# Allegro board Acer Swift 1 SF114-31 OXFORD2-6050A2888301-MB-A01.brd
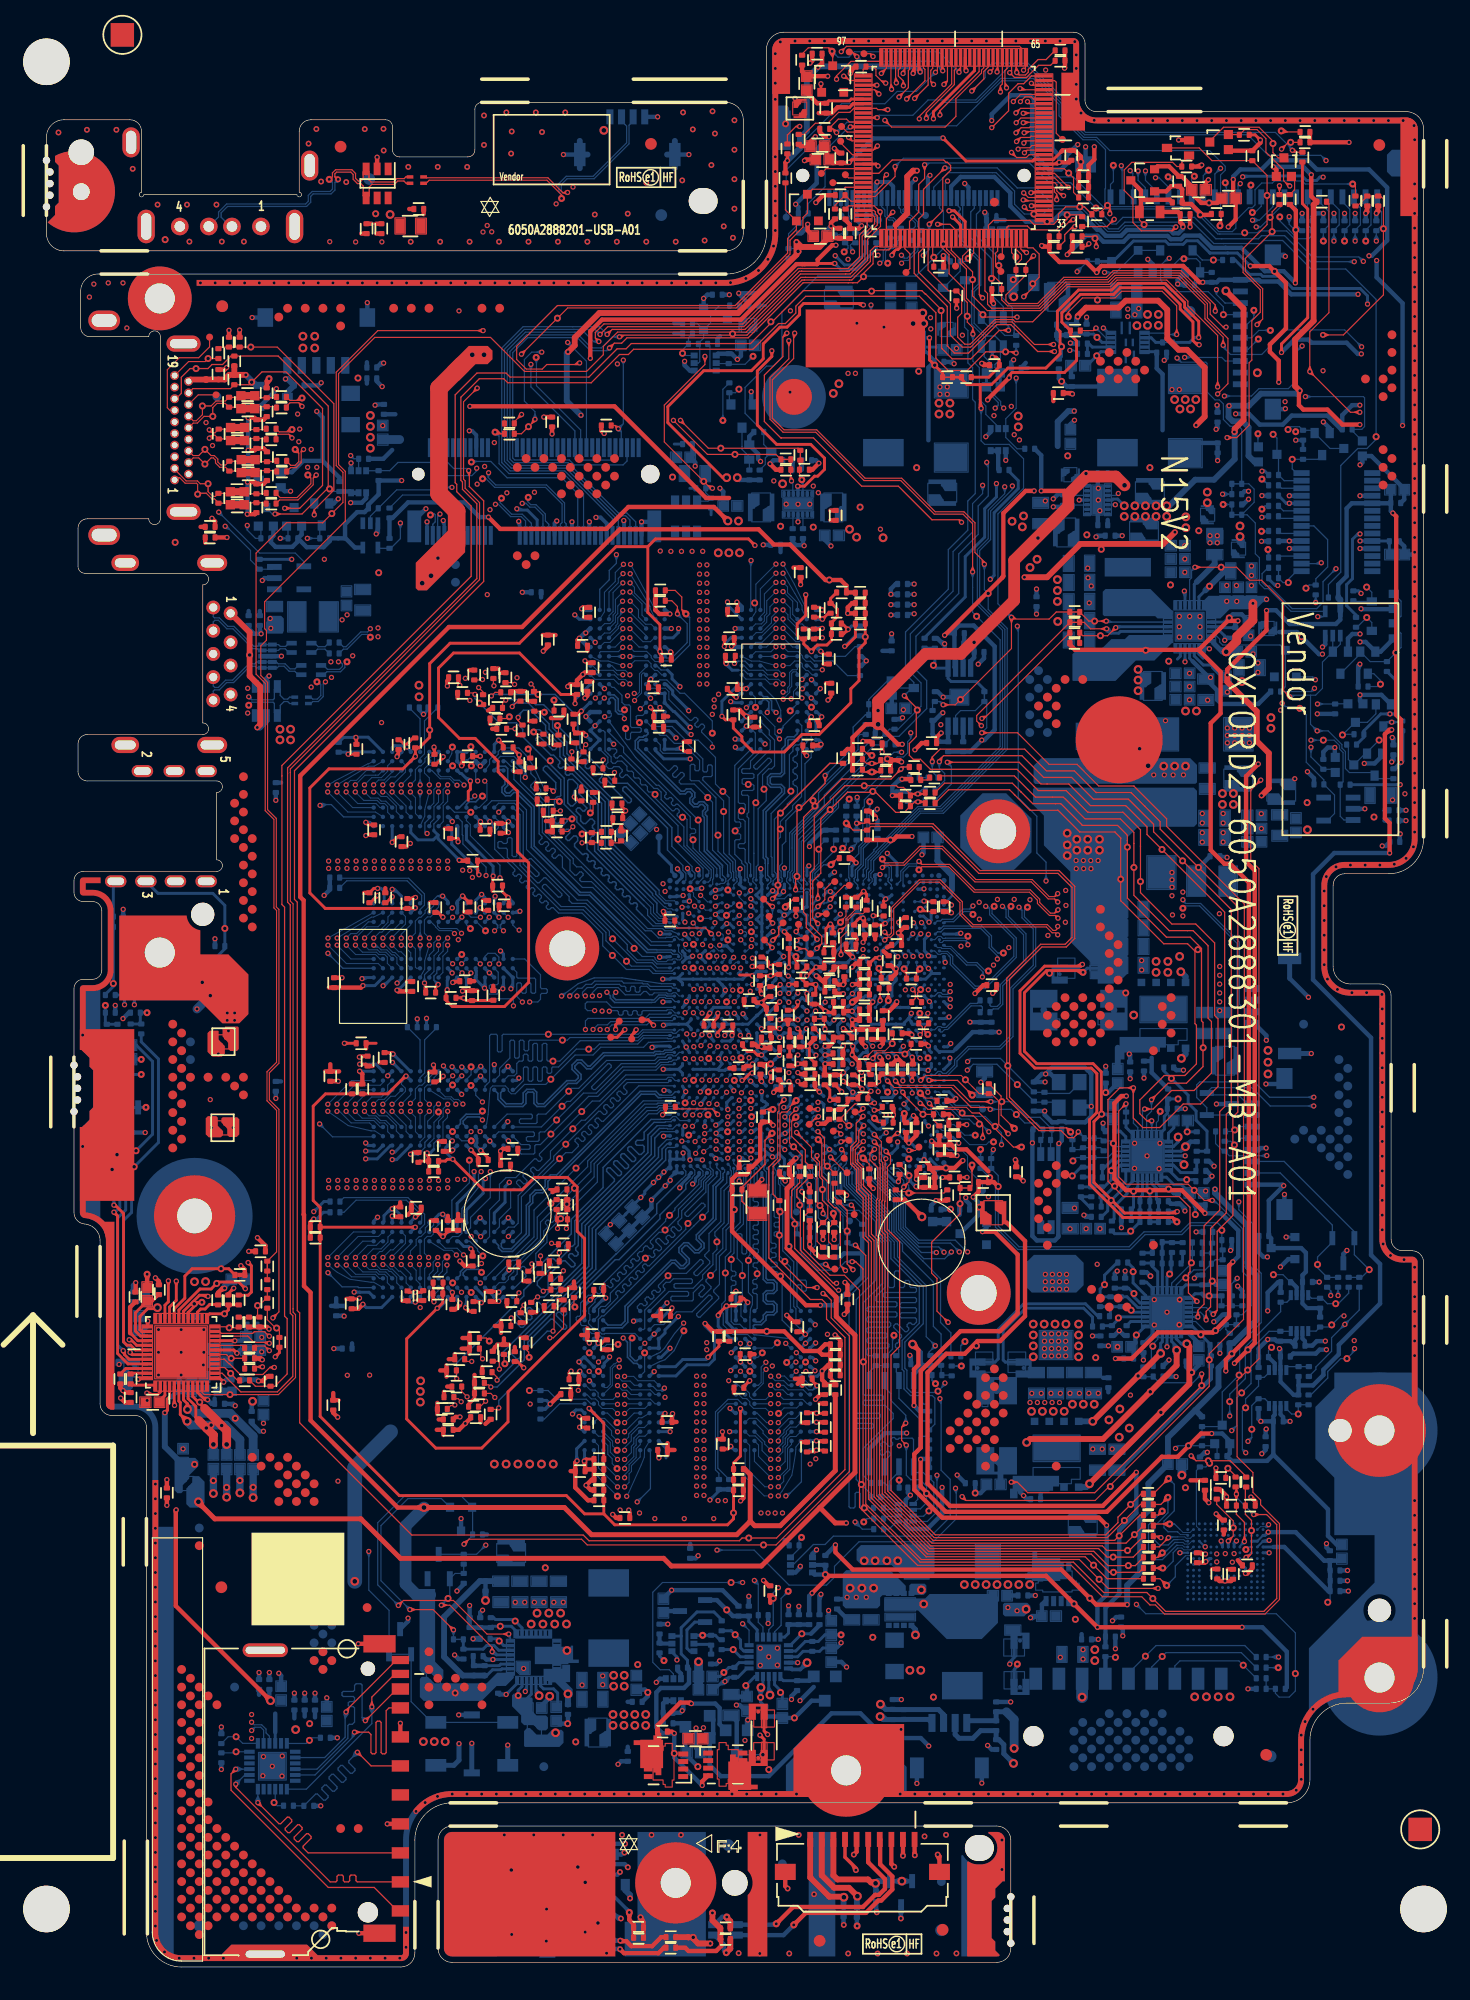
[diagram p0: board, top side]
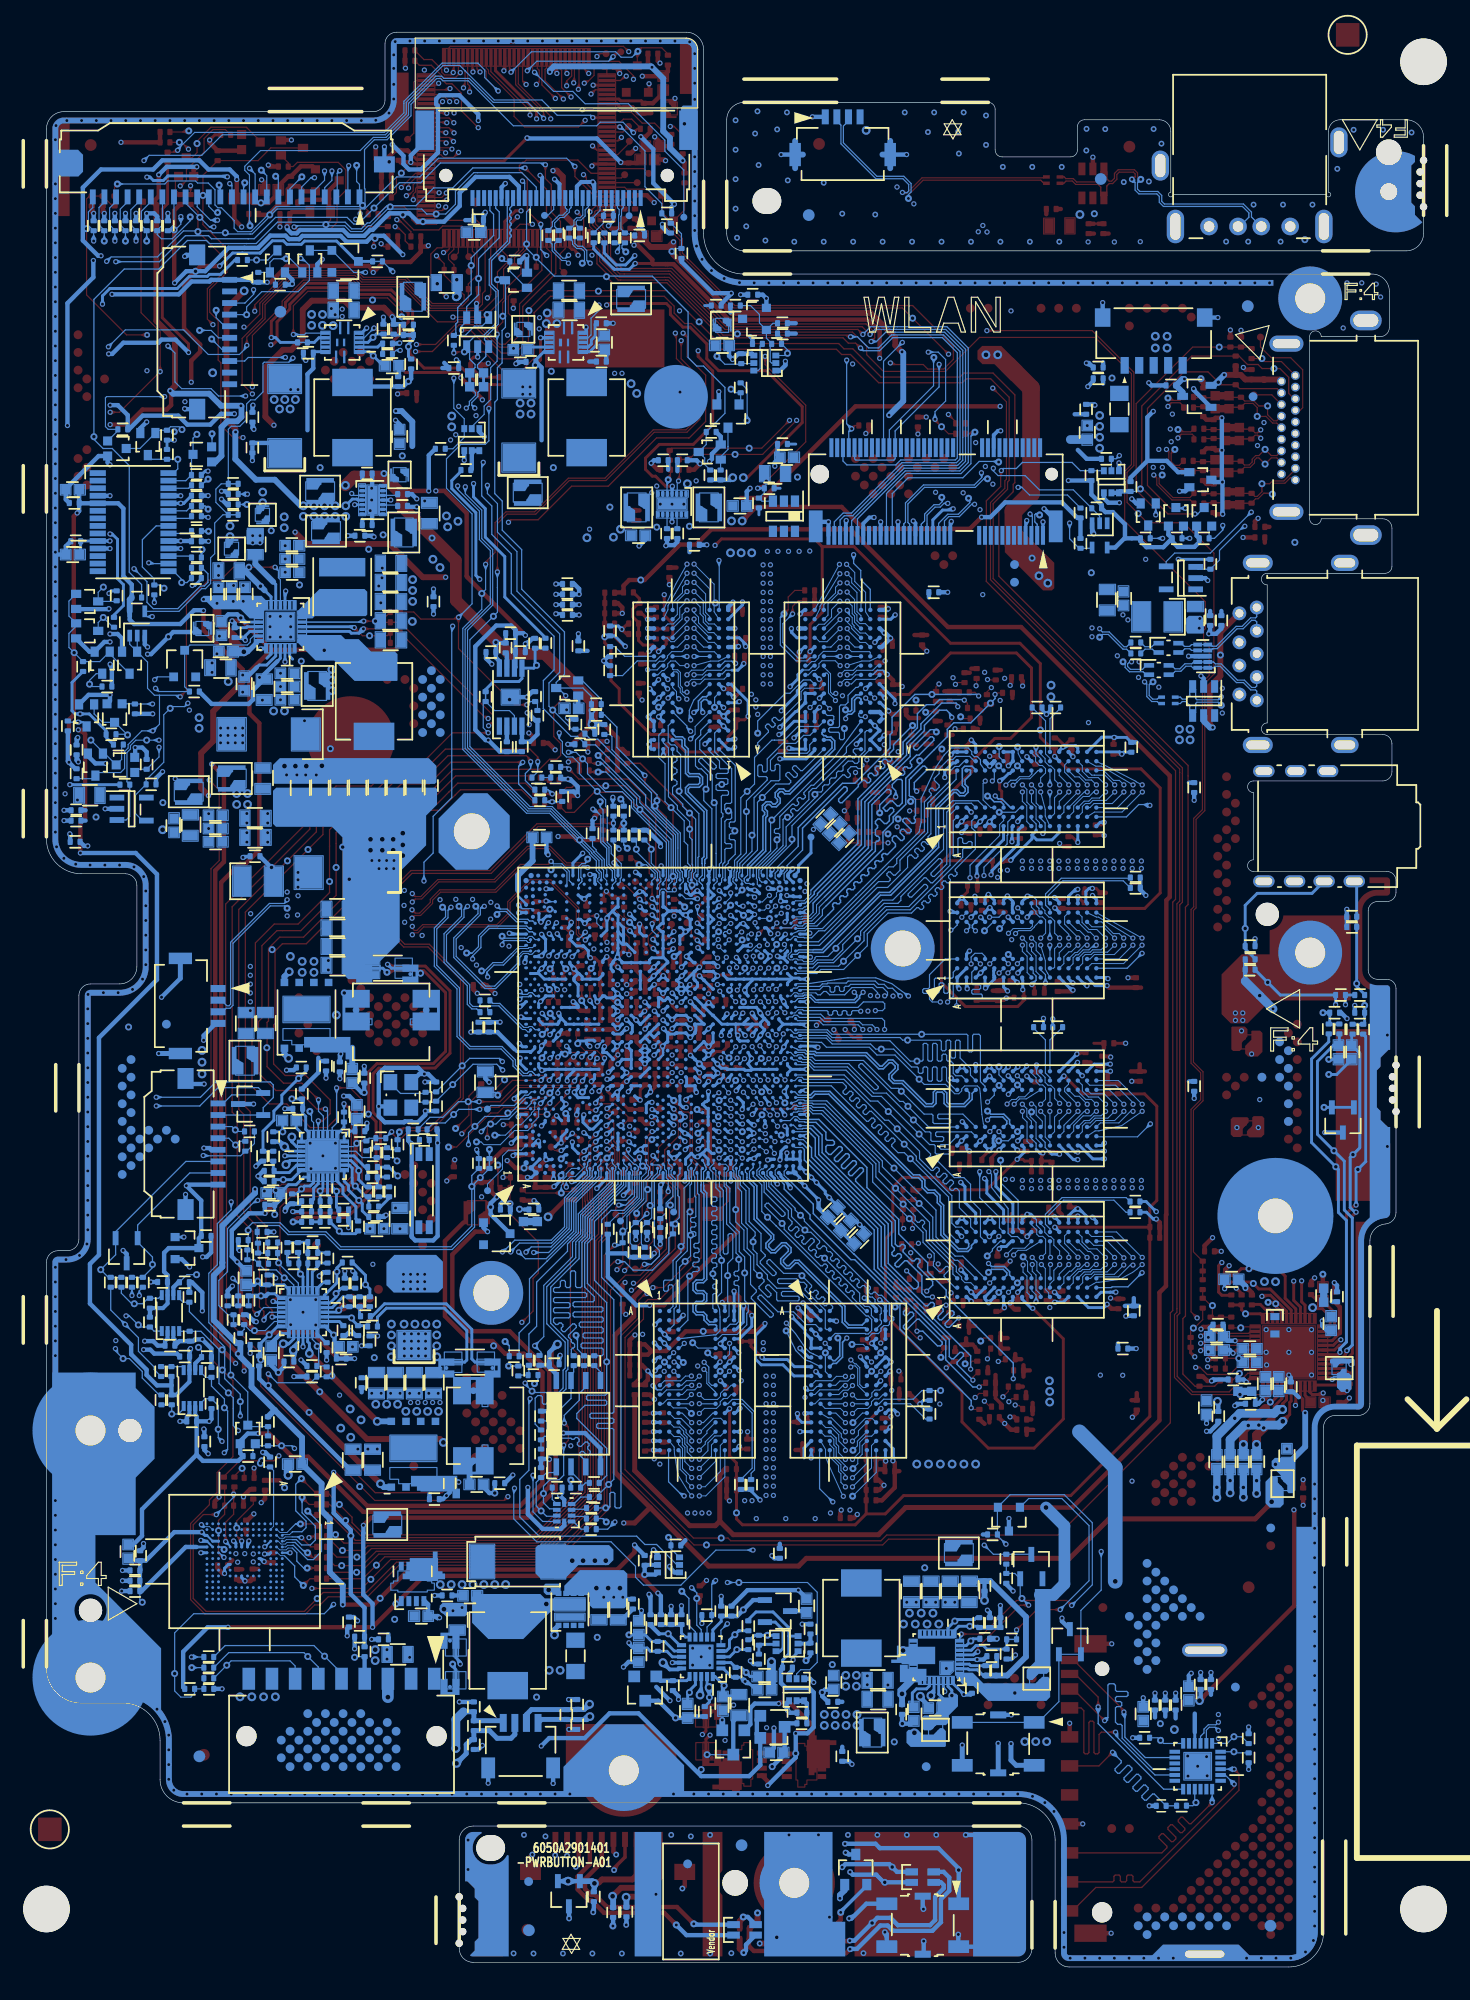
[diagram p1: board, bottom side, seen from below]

Outline 118.77 x 166.8 mm; copper layers: TOP, L2, L3, L4, L5, BOTTOM. Coordinates in mm from the lower left corner of the outline.
Outline path: 0,157.75 arc(0.44,158.81) 1.5,159.25 7.2,159.25 arc(7.91,158.96) 8.2,158.25 8.2,153 arc(8.06,152.66) 8.4,152.8 21.6,152.8 arc(21.94,152.66) 21.8,153 21.8,158.25 arc(22.09,158.96) 22.8,159.25 29.25,159.25 arc(29.67,159.07) 29.85,158.65 29.85,156.65 arc(30.03,156.23) 30.45,156.05 36.35,156.05 arc(36.77,156.23) 36.95,156.65 36.95,160.15 arc(37.13,160.57) 37.55,160.75 58.6,160.75 arc(59.66,160.31) 60.1,159.25 60.1,149.45 arc(59.66,148.39) 58.6,147.95 1.5,147.95 arc(0.44,148.39) 0,149.45 0,157.75 ; 2.37,93.65 arc(2.61,94.22) 3.17,94.45 14.68,94.45 arc(15.18,94.95) 14.68,95.45 14.68,101.25 arc(15.18,101.75) 14.68,102.25 3.53,102.25 arc(2.96,102.48) 2.72,103.05 2.72,105.45 arc(2.96,106.02) 3.53,106.25 13.49,106.25 arc(13.99,106.75) 13.49,107.25 13.49,119.15 arc(13.99,119.65) 13.49,120.15 3.33,120.15 arc(2.9,120.33) 2.72,120.75 2.72,124.05 arc(2.96,124.62) 3.53,124.85 8.82,124.85 arc(9.32,124.35) 9.82,124.85 9.82,140.55 arc(9.32,141.05) 8.82,140.55 3.75,140.55 arc(3.18,140.78) 2.95,141.35 2.95,144.45 arc(3.39,145.51) 4.45,145.95 58.6,145.95 arc(61.07,146.98) 62.1,149.45 62.1,165.3 arc(62.54,166.36) 63.6,166.8 88.58,166.8 arc(89.28,166.51) 89.58,165.8 89.58,160.95 arc(89.87,160.24) 90.58,159.95 117.28,159.95 arc(118.34,159.51) 118.77,158.45 118.77,97.25 arc(117.9,95.13) 115.77,94.25 111.98,94.25 arc(111.27,93.96) 110.98,93.25 110.98,86.25 arc(111.41,85.19) 112.48,84.75 114.98,84.75 arc(115.68,84.46) 115.98,83.75 115.98,62.75 arc(116.27,62.04) 116.98,61.75 117.77,61.75 arc(118.48,61.46) 118.77,60.75 118.77,25.75 arc(117.9,23.63) 115.77,22.75 112.18,22.75 arc(109.91,21.81) 108.98,19.55 108.98,16.15 arc(108.39,14.74) 106.97,14.15 34.98,14.15 arc(32.71,13.21) 31.78,10.95 31.78,1.2 arc(31.42,0.35) 30.57,0 11.63,0 arc(9.5,0.88) 8.63,3 8.63,46.55 arc(8.33,47.26) 7.63,47.55 5.63,47.55 arc(4.92,47.84) 4.63,48.55 4.63,62.61 arc(4.24,63.59) 3.29,64.05 arc(2.64,64.37) 2.37,65.05 2.37,84.35 arc(2.61,84.92) 3.17,85.15 3.98,85.15 arc(4.54,85.38) 4.77,85.95 4.77,91.05 arc(4.54,91.62) 3.98,91.85 3.17,91.85 arc(2.61,92.08) 2.37,92.65 2.37,93.65 ; 33.78,10.95 arc(34.13,11.8) 34.98,12.15 81.97,12.15 arc(82.82,11.8) 83.18,10.95 83.18,1.6 arc(82.82,0.75) 81.97,0.4 34.98,0.4 arc(34.13,0.75) 33.78,1.6 33.78,10.95

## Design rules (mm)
net group BATT_IN: nets BATT_IN UNNAMED_5_CN09_I103_7
net group CLK_KBPCI: nets CLK_KBPCI CLK_KBPCI_R
net group CLK_PCIE_WLAN_D: nets CLK_PCIE_WLAN_DN CLK_PCIE_WLAN_DP
net group COREPWROK: nets COREPWROK SB_PWRGD
net group CPU_PROCHOT#: nets CPU_PROCHOT# CPU_PROCHOT#_R
net group E-USB2_P4_CN1300: nets USB_WLAN_DN USB_WLAN_DP
net group EC_BKLTEN: nets EC_BKLTEN EDP_BKLTEN
net group EC_RSMRST#: nets EC_RSMRST# MOIC_RSMRST
net group EC_SMB1_CLK: nets EC_SMB1_CLK UNNAMED_5_CN09_I103_5
net group EC_SMB1_DATA: nets EC_SMB1_DATA UNNAMED_5_CN09_I103_6
net group EC_SPI_CLK: nets EC_SPI_CLK EC_SPI_R_CLK
net group EC_SPI_CS0#: nets EC_SPI_CS0# EC_SPI_R_CS0#
net group EN_1V05A: nets EN_1V05A UNNAMED_12_CSC0402_I17_A
net group EN_5V: nets EN_5V UNNAMED_15_APL3523A_I202_3
net group EN_5VLDO: nets EN_5VLDO UNNAMED_6_CSC0402_I64_A
net group EN_PVCORE: nets EN_PVCORE PVGG_PG
net group EN_VDDQ: nets EN_VDDQ SLP_S4#_3R
net group HDA_R_SDIN0: nets HDA_R_SDIN0 HDA_SDIN0
net group HDA_RST#: nets HDA_RST# UNNAMED_36_540276_I157_MFHDARST
net group HDA_SDOUT: nets HDA_SDOUT UNNAMED_36_540276_I157_MFHDASDO
net group HDA_SYNC: nets HDA_SYNC UNNAMED_36_540276_I157_MFHDASYN
net group HDMI_HPD_CN: nets HDMI_HPD_CN UNNAMED_27_099A4AC19HBLBNF_I1_2
net group HPS: nets HPS UNNAMED_51_ALC233VB2CGT_I110_HP
net group INV_PWM_APU_1V8: nets INV_PWM_APU_1V8 UNNAMED_54_NPND_I136_B
net group KBRST#: nets KBRST# UNNAMED_37_540276_I161_I2C6SDA
net group LPC_DATA: nets TPM_LPCPD# TPM_SERIRQ
net group M_A_DQS0_D: nets M_A_DQS0_DN M_A_DQS0_DP
net group M_A_DQS1_D: nets M_A_DQS1_DN M_A_DQS1_DP
net group M_A_DQS2_D: nets M_A_DQS2_DN M_A_DQS2_DP
net group M_A_DQS3_D: nets M_A_DQS3_DN M_A_DQS3_DP
net group M_A_DQS4_D: nets M_A_DQS4_DN M_A_DQS4_DP
net group M_A_DQS5_D: nets M_A_DQS5_DN M_A_DQS5_DP
net group M_A_DQS6_D: nets M_A_DQS6_DN M_A_DQS6_DP
net group M_A_DQS7_D: nets M_A_DQS7_DN M_A_DQS7_DP
net group M_B_DQS0_D: nets M_B_DQS0_DN M_B_DQS0_DP
net group M_B_DQS1_D: nets M_B_DQS1_DN M_B_DQS1_DP
net group M_B_DQS2_D: nets M_B_DQS2_DN M_B_DQS2_DP
net group M_B_DQS3_D: nets M_B_DQS3_DN M_B_DQS3_DP
net group M_B_DQS4_D: nets M_B_DQS4_DN M_B_DQS4_DP
net group M_B_DQS5_D: nets M_B_DQS5_DN M_B_DQS5_DP
net group M_B_DQS6_D: nets M_B_DQS6_DN M_B_DQS6_DP
net group M_B_DQS7_D: nets M_B_DQS7_DN M_B_DQS7_DP
net group MIC_IN_CLK: nets MIC_IN_CLK MIC_IN_CLK_R
net group MIC_IN_DATA: nets MIC_IN_DATA MIC_IN_DATA_R
net group MISC-CLK: nets CLKREQ_WLAN1V8# CLKREQ_WLAN#
net group MMC1_CLK: nets MMC1_CLK MMC1_CLK_R
net group MMC1_CMD: nets MMC1_CMD MMC1_CMD_R
net group MMC1_D0: nets MMC1_D0 MMC1_D0_R
net group MMC1_D1: nets MMC1_D1 MMC1_D1_R
net group MMC1_D2: nets MMC1_D2 MMC1_D2_R
net group MMC1_D3: nets MMC1_D3 MMC1_D3_R
net group MMC1_D4: nets MMC1_D4 MMC1_D4_R
net group MMC1_D5: nets MMC1_D5 MMC1_D5_R
net group MMC1_D6: nets MMC1_D6 MMC1_D6_R
net group MMC1_D7: nets MMC1_D7 MMC1_D7_R
net group PCH_SPI_CLK: nets PCH_SPI_CLK SPI_SOC_R_CLK
net group PCH_SPI_CS0#: nets PCH_SPI_CS0# SPI_SOC_R_CS0#
net group PCH_SPI_IO2: nets PCH_SPI_IO2 SPI_WP#
net group PCH_SPI_IO3: nets PCH_SPI_IO3 SPI_HOLD
net group PCI_3S_CLKRUN#: nets PCI_3S_CLKRUN# TPM_CLKRUN
net group PCIE_OBSN: nets PCIE_OBSN PCIE_OBSP
net group PCIE_WLAN_RX_D: nets PCIE_WLAN_RX_DN PCIE_WLAN_RX_DP
net group SATA_OBS: nets SATA_OBSN SATA_OBSP
net group SD_CLK: nets SD_CLK SD_R_CLK
net group SD_DATA: nets SD_CD# SD_WP
net group SDDR_RESET: nets MEM_RST0# MEM_RST1_N
net group SLP_S3#_3R: nets SLP_S3#_3R UNNAMED_13_RSC0402_I94_B
net group SUS_PWR_DN_ACK: nets SUS_PWR_DN_ACK UNNAMED_13_RSCSHORT_I99_B
net group THRM_SHUTDWN#: nets THRM_SHUTDWN# UNNAMED_45_AT9667_I14_5
net group TSENSE: nets TSENSE UNNAMED_8_RSC0402_I48_A
net group UNNAMED_12_CSC0603_I125_A: nets UNNAMED_12_CSC0603_I125_A UNNAMED_12_NMOSDUALC_I91_D1
net group UNNAMED_35_540276_I159_DDI0PLLO: nets UNNAMED_35_540276_I159_DDI0PL_1 UNNAMED_35_540276_I159_DDI0PLLO
net group UNNAMED_35_540276_I159_DDI1PLLO: nets UNNAMED_35_540276_I159_DDI1PL_1 UNNAMED_35_540276_I159_DDI1PLLO
net group UNNAMED_45_AT9667_I14_7: nets UNNAMED_45_AT9667_I14_7 UNNAMED_45_AT9667_I14_8
net group UNNAMED_51_ALC233VB2CGT_I110_CB: nets UNNAMED_51_ALC233VB2CGT_I110__1 UNNAMED_51_ALC233VB2CGT_I110_CB
net group UNNAMED_54_CSC0402_I105_A: nets UNNAMED_54_CSC0402_I105_A UNNAMED_54_NMOSDUALC_I102_D2
net group USB3_OBS: nets USB3_OBSN USB3_OBSP
net group USB_P2_D: nets USB_P2_DN USB_P2_DP
net group VGG_TSENSE: nets UNNAMED_10_RSC0402_I48_A VGG_TSENSE
net group VNN_SENSEP: nets VNN_SENSE_R VNN_SENSEP
net group XTAL_SOC_IN: nets XTAL_SOC_IN XTAL_SOC_OUT
net group AUDIO-B: nets PCSPKR
net group BEEP: nets BEEP UNNAMED_51_ALC233VB2CGT_I110_PC UNNAMED_51_CSC0402_I68_B UNNAMED_51_RSC0402_I136_B
net group CAM_PWR#: nets CAM_PWR# UNNAMED_54_CSC0402_I39_A UNNAMED_54_CSC0402_I39_B UNNAMED_54_CSC0402_I43_A
net group CLK_PCI_DEBUG: nets CLK_PCI_DEBUG CLK_TPM TPM_LPC_CLK UNNAMED_59_540276_I142_MFLPCCLK UNNAMED_59_RSC0402_I187_B
net group EC_SPI_SI_IO0: nets EC_SPI_SI_IO0 PCH_SPI_SI SPI_SI_IO0
net group EC_SPI_SO_IO1: nets EC_SPI_SO_IO1 PCH_SPI_SO SPI_SO_IO1
net group EC_WLAN_PCIE_WAKE#: nets EC_WLAN_PCIE_WAKE# PCIE_WAKE# PMU_PCIE_WAKE# UNNAMED_21_APCI0062P001A_I66_PE UNNAMED_46_NPCE985LB1DX_I256_GP
net group EN_PVGG: nets EN_PVGG EN_VTT SLP_S3#_3R_IC UNNAMED_15_APL3523A_I201_3 UNNAMED_15_APL3523A_I201_5 UNNAMED_15_APL3523A_I202_5
net group HDA_BITCLK: nets HDA_BITCLK HDA_R_BITCLK UNNAMED_36_540276_I157_MFHDACLK
net group HDMI_DDC: nets HDMI_CN_DDCCLK HDMI_CN_DDCDATA HDMI_DDC_CLK HDMI_DDC_DAT
net group HDMI_TX0_C_DN: nets HDMI_TX0_C_DN HDMI_TX0_DN HDMI_TX0_R_DN
net group HDMI_TX0_C_DP: nets HDMI_TX0_C_DP HDMI_TX0_DP HDMI_TX0_R_DP
net group HDMI_TX1_C_DN: nets HDMI_TX1_C_DN HDMI_TX1_DN HDMI_TX1_R_DN
net group HDMI_TX1_C_DP: nets HDMI_TX1_C_DP HDMI_TX1_DP HDMI_TX1_R_DP
net group HDMI_TX2_C_DN: nets HDMI_TX2_C_DN HDMI_TX2_DN HDMI_TX2_R_DN
net group HDMI_TX2_C_DP: nets HDMI_TX2_C_DP HDMI_TX2_DP HDMI_TX2_R_DP
net group HDMI_TXCL_DN: nets HDMI_TXC_C_DN HDMI_TXC_R_DN HDMI_TXCL_DN
net group HDMI_TXCL_DP: nets HDMI_TXC_C_DP HDMI_TXC_R_DP HDMI_TXCL_DP
net group HP_L: nets HP_L LINE1_L LINE1_REF_L UNNAMED_52_2SJ3095078111F_I61_1
net group HP_R: nets HP_R LINE1_R LINE1_REF_R UNNAMED_52_2SJ3095078111F_I61_2
net group LOW: nets SB_PWRBTN#
net group LPC_3S_AD<0>: nets TPM_LPC_AD<0>
net group LPC_3S_AD<1>: nets TPM_LPC_AD<1>
net group LPC_3S_AD<2>: nets TPM_LPC_AD<2>
net group LPC_3S_AD<3>: nets TPM_LPC_AD<3>
net group LPC_3S_FRAME#: nets TPM_LPC_FRAME#
net group MIC: nets MIC MIC2_REF RING2 RING2_CONN SLEEVE
net group MISC_OTHER: nets PLT_RST#
net group MMC1_RST#: nets MMC1_RST# UNNAMED_24_RSC0402_I113_A UNNAMED_36_540276_I157_SATAGP0
net group MMC_DATA: nets MMC1_RCLK
net group OTHER_CLK: nets IM_CLK_5
net group OTHER_DATA: nets IM_DAT_5
net group PWR: nets 3V3A_PG 5V_PG P0V675M_VREF P3V3_TOUCHPAD P3V3A_PRIME P3V3AL_EC P3V3AL_PB P3V3AL_R P3V3S_CAM P5V0A_PBN P5V0S_HDMI_CRT P5VAUXON
net group RTC_CLK: nets RTC_RST_N RTC_TEST_N RTCX1 RTCX2
net group SCLK: nets GPS_32K_CLK
net group SDDR_A_BYTE0: nets M_A_DM<0> M_A_DQ<0> M_A_DQ<1> M_A_DQ<2> M_A_DQ<3> M_A_DQ<4> M_A_DQ<5> M_A_DQ<6> M_A_DQ<7>
net group SDDR_A_BYTE1: nets M_A_DM<1> M_A_DQ<8> M_A_DQ<9> M_A_DQ<10> M_A_DQ<11> M_A_DQ<12> M_A_DQ<13> M_A_DQ<14> M_A_DQ<15>
net group SDDR_A_BYTE2: nets M_A_DM<2> M_A_DQ<16> M_A_DQ<17> M_A_DQ<18> M_A_DQ<19> M_A_DQ<20> M_A_DQ<21> M_A_DQ<22> M_A_DQ<23>
net group SDDR_A_BYTE3: nets M_A_DM<3> M_A_DQ<24> M_A_DQ<25> M_A_DQ<26> M_A_DQ<27> M_A_DQ<28> M_A_DQ<29> M_A_DQ<30> M_A_DQ<31>
net group SDDR_A_BYTE4: nets M_A_DM<4> M_A_DQ<32> M_A_DQ<33> M_A_DQ<34> M_A_DQ<35> M_A_DQ<36> M_A_DQ<37> M_A_DQ<38> M_A_DQ<39>
net group SDDR_A_BYTE5: nets M_A_DM<5> M_A_DQ<40> M_A_DQ<41> M_A_DQ<42> M_A_DQ<43> M_A_DQ<44> M_A_DQ<45> M_A_DQ<46> M_A_DQ<47>
net group SDDR_A_BYTE6: nets M_A_DM<6> M_A_DQ<48> M_A_DQ<49> M_A_DQ<50> M_A_DQ<51> M_A_DQ<52> M_A_DQ<53> M_A_DQ<54> M_A_DQ<55>
net group SDDR_A_BYTE7: nets M_A_DM<7> M_A_DQ<56> M_A_DQ<57> M_A_DQ<58> M_A_DQ<59> M_A_DQ<60> M_A_DQ<61> M_A_DQ<62> M_A_DQ<63>
net group SDDR_B_BYTE0: nets M_B_DM<0> M_B_DQ<0> M_B_DQ<1> M_B_DQ<2> M_B_DQ<3> M_B_DQ<4> M_B_DQ<5> M_B_DQ<6> M_B_DQ<7>
net group SDDR_B_BYTE1: nets M_B_DM<1> M_B_DQ<8> M_B_DQ<9> M_B_DQ<10> M_B_DQ<11> M_B_DQ<12> M_B_DQ<13> M_B_DQ<14> M_B_DQ<15>
net group SDDR_B_BYTE2: nets M_B_DM<2> M_B_DQ<16> M_B_DQ<17> M_B_DQ<18> M_B_DQ<19> M_B_DQ<20> M_B_DQ<21> M_B_DQ<22> M_B_DQ<23>
net group SDDR_B_BYTE3: nets M_B_DM<3> M_B_DQ<24> M_B_DQ<25> M_B_DQ<26> M_B_DQ<27> M_B_DQ<28> M_B_DQ<29> M_B_DQ<30> M_B_DQ<31>
net group SDDR_B_BYTE4: nets M_B_DM<4> M_B_DQ<32> M_B_DQ<33> M_B_DQ<34> M_B_DQ<35> M_B_DQ<36> M_B_DQ<37> M_B_DQ<38> M_B_DQ<39>
net group SDDR_B_BYTE5: nets M_B_DM<5> M_B_DQ<40> M_B_DQ<41> M_B_DQ<42> M_B_DQ<43> M_B_DQ<44> M_B_DQ<45> M_B_DQ<46> M_B_DQ<47>
net group SDDR_B_BYTE6: nets M_B_DM<6> M_B_DQ<48> M_B_DQ<49> M_B_DQ<50> M_B_DQ<51> M_B_DQ<52> M_B_DQ<53> M_B_DQ<54> M_B_DQ<55>
net group SDDR_B_BYTE7: nets M_B_DM<7> M_B_DQ<56> M_B_DQ<57> M_B_DQ<58> M_B_DQ<59> M_B_DQ<60> M_B_DQ<61> M_B_DQ<62> M_B_DQ<63>
net group SDDR_VREF: nets M_A_OCAVREF M_A_ODQVREF M_B_OCAVREF M_B_ODQVREF P0V675M_MA_VERF_CA P0V675M_MA_VERF_DQ P0V675M_MB_VERF_CA P0V675M_MB_VERF_DQ
net group SM_RCOMP: nets DDR3_M0_RCOMPPD DDR3_M1_RCOMPPD SDMMC1_RCOMP SDMMC3_RCOMP
net group SMB_CLK: nets EC_SCI# EC_SMB2_CLK PCU_SMB_CLK SIO_I2C_CLK
net group SMB_DATA: nets EC_SMB2_DATA PCU_SMB_DATA SIO_I2C_DATA
net group SOC_SMBCLK: nets I2CO_SCL I2CO_SCL_TP SOC_SMBCLK UNNAMED_37_RSC0402_I274_A UNNAMED_46_NPCE985LB1DX_I255__4
net group SOC_SMBDAT: nets I2CO_SDA I2CO_SDA_TP SOC_SMBDAT UNNAMED_37_RSC0402_I275_A UNNAMED_46_NPCE985LB1DX_I255__5
net group SPI_CLK: nets SPI_CLK
net group SPI_DATA: nets SPI_CS0#
net group SPK_OUT_L_N: nets SPK_OUT_L_N SPK_OUT_L_P SPK_OUT_R_L_N SPK_OUT_R_L_P
net group SPK_OUT_R_N: nets SPK_OUT_R_N SPK_OUT_R_P SPK_OUT_R_R_N SPK_OUT_R_R_P
net group SVID_ALERT: nets SVID_ALERT VR_SVID_VCC_ALERT# VR_SVID_VGG_ALERT#
net group SVID_CLK: nets SVID_CLK VR_SVID_VCC_CLK VR_SVID_VGG_CLK
net group SVID_DATA: nets SVID_DATA UNNAMED_42_RSC0402_I10_A UNNAMED_42_RSC0402_I11_A VR_SVID_VCC_DATA VR_SVID_VGG_DATA
net group TP_INT#: nets TP_INT# UNNAMED_16_505030084N001_I222_3 UNNAMED_16_505030084N001_I222_4 UNNAMED_46_NPCE985LB1DX_I255_GP
net group UART: nets EC_SMI#
net group UNNAMED_8_CSC0402_I40_A: nets UNNAMED_8_CSC0402_I40_A UNNAMED_8_CSC0402_I40_B UNNAMED_8_CSC0402_I41_B UNNAMED_8_CSC0402_I44_B UNNAMED_8_NCP81101BMNTXG_I71_25
net group UNNAMED_8_CSC0402_I57_A: nets UNNAMED_8_CSC0402_I57_A UNNAMED_8_CSC0402_I57_B UNNAMED_8_NCP81101BMNTXG_I71_21
net group UNNAMED_10_CSC0402_I40_A: nets UNNAMED_10_CSC0402_I40_A UNNAMED_10_CSC0402_I40_B UNNAMED_10_CSC0402_I41_B UNNAMED_10_CSC0402_I44_B UNNAMED_10_NCP81101BMNTXG_I71_5
net group UNNAMED_10_CSC0402_I56_A: nets UNNAMED_10_CSC0402_I56_A UNNAMED_10_CSC0402_I56_B UNNAMED_10_NCP81101BMNTXG_I71_3
net group USB_RCOMP: nets USB_RCOMP
net group VCC0_SENSEN_R: nets UNNAMED_8_CSC0402_I35_A UNNAMED_8_CSC0402_I35_B UNNAMED_8_CSC0402_I36_B VCC0_SENSEN_R VCC0_SENSEP_R VCC1_SENSEN_R VCC1_SENSEP_R VCC_SENSEN VCC_SENSEP
net group VGG_SENSEN: nets UNNAMED_10_CSC0402_I35_A UNNAMED_10_CSC0402_I35_B UNNAMED_10_CSC0402_I36_B VGG_SENSEN VGG_SENSEN_R VGG_SENSEP VGG_SENSEP_R
net group VRA: nets VRA3V3A_VCC VRA3V3A_VCLK VRA5V0A_VCC VRACHG_ACDET VRACHG_ACDRV VRACHG_ACN VRACHG_ACP VRACHG_BATDRV VRACHG_BATDRV1 VRACHG_BST VRACHG_BST1 VRACHG_CMSRC VRACHG_HG VRACHG_ILIM VRACHG_PH VRACHG_SNB VRACHG_SRN VRACHG_SRP VRACHG_VCC VRACPU_BST VRACPU_BST1 VRACPU_CSN1 VRACPU_CSP1 VRACPU_VDD VRAVDDQ_BST VRAVDDQ_BST1 VRAVDDQ_CS VRAVDDQ_SET VRAVDDQ_SNB VRAVDDQ_TON VRAVGG_BST VRAVGG_BST1 VRAVGG_CSN1 VRAVGG_CSP1 VRAVGG_ON VRAVGG_VDD VRAVR_ON
net group VRB: nets VRB3V3A_BST VRB3V3A_BST1 VRB5V0A_BST VRB5V0A_BST1 VRB_VCC VRB_VDD5
net group VRP: nets VRP1V05A_PH VRP1V8A_PH VRPCHG_LG VRPVCORE_HG1 VRPVCORE_LG1 VRPVDDQ_VLDOIN VRPVGG_HG1 VRPVGG_LG1 VRPVTT VRPVTT_REF

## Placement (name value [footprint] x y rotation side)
B500  -  [PASSWORD_0805]  61.31 65.94 90 top
C13  CSC0402_DY  [CSC_100X050X040_2]  63.78 129.08 180 top
C14  0.1uF_16V_2  [CSC_100X050X040_2]  74.98 51.97 180 bottom
C18  22pF_50V_2  [CSC_100X050X040_2]  19.33 50.49 90 top
C300  0.1uF_16V_2  [CSC_100X050X040_2]  68.55 155.96 90 top
C301  0.1uF_16V_2  [CSC_100X050X040_2]  89.46 153.47 0 top
C302  0.1uF_16V_2  [CSC_100X050X040_2]  89.46 154.38 0 top
C303  0.1uF_16V_2  [CSC_100X050X040_2]  88.39 156.18 270 top
C304  0.1uF_16V_2  [CSC_100X050X040_2]  66.47 164.95 180 top
C305  0.1uF_16V_2  [CSC_100X050X040_2]  67.26 160.25 270 top
C306  0.1uF_16V_2  [CSC_100X050X040_2]  68.4 149.47 90 top
C310  1uF_6.3V_2  [CSC_100X050X040_2]  89.46 152.55 0 top
C312  10uF_6.3V_3_DY  [CSC_160X080X080_2]  66.75 149.22 180 top
C313  4.7uF_6.3V_3  [CSC_160X080X080_2]  66.93 155.83 180 top
C316  0.1uF_16V_2  [CSC_100X050X040_2]  76.96 146.58 0 top
C351  CSC0402_DY  [CSC_100X050X040_2]  64 147.73 270 bottom
C501  10uF_6.3V_3  [CSC_160X080X080_2]  8.68 58.01 90 top
C502  2.2uF_6.3V_2  [CSC_100X050X040_2]  7.67 57.76 270 top
C503  1uF_6.3V_2  [CSC_100X050X040_2]  6.37 50.7 90 top
C504  4.7uF_10V_3  [CSC_160X080X080_2]  7.97 55.5 270 bottom
C505  0.1uF_16V_2  [CSC_100X050X040_2]  7.46 57.78 90 bottom
C506  CSC0402_DY  [CSC_100X050X040_2]  17.47 55.6 90 top
C507  0.1uF_16V_2  [CSC_100X050X040_2]  16.58 55.6 90 top
C508  10uF_6.3V_3  [CSC_160X080X080_2]  17.83 54.33 0 bottom
C509  0.1uF_16V_2  [CSC_100X050X040_2]  17.73 55.37 0 bottom
C510  22pF_50V_2_DY  [CSC_100X050X040_2]  17.52 52.48 0 top
C511  1uF_6.3V_2  [CSC_100X050X040_2]  7.26 50.7 90 top
C512  10uF_6.3V_3  [CSC_160X080X080_2]  9.14 48.69 0 top
C513  10uF_6.3V_3  [CSC_160X080X080_2]  11.78 44.07 90 bottom
C514  0.1uF_16V_2  [CSC_100X050X040_2]  14.93 48.56 0 bottom
C515  10uF_6.3V_3  [CSC_160X080X080_2]  13.64 50.27 90 bottom
C516  0.1uF_16V_2  [CSC_100X050X040_2]  16.43 50.65 0 bottom
C517  10uF_6.3V_3  [CSC_160X080X080_2]  14.98 52.15 180 bottom
C519  0.1uF_16V_2_DY  [CSC_100X050X040_2]  17.7 47.47 270 bottom
C520  0.1uF_16V_2  [CSC_100X050X040_2]  11.45 50.01 90 bottom
C521  10uF_6.3V_3  [CSC_160X080X080_2]  12.49 50.27 90 bottom
C522  10uF_6.3V_3_DY  [CSC_160X080X080_2]  18.72 48.23 270 bottom
C523  CSC0402_DY  [CSC_100X050X040_2]  18.46 61.7 0 top
C524  CSC0402_DY  [CSC_100X050X040_2]  7.26 49.1 90 top
C525  CSC0402_DY  [CSC_100X050X040_2]  10.39 40.87 270 top
C530  10uF_6.3V_3  [CSC_160X080X080_2]  17.83 53.19 0 bottom
C531  4.7uF_6.3V_3  [CSC_160X080X080_2]  16.56 59.28 180 bottom
C532  10uF_6.3V_3  [CSC_160X080X080_2]  14.98 53.29 180 bottom
C600  470pF_50V_2_DY  [CSC_100X050X040_2]  7.67 82.27 180 bottom
C601  470pF_50V_2_DY  [CSC_100X050X040_2]  5.51 82.27 0 bottom
C602  4.7uF_6.3V_3  [CSC_160X080X080_2]  7.34 78.87 90 bottom
C603  4.7uF_6.3V_3  [CSC_160X080X080_2]  6.19 78.87 90 bottom
C604  CSC0402_DY  [CSC_100X050X040_2]  6.19 89.66 0 bottom
C605  CSC0402_DY  [CSC_100X050X040_2]  14.96 88.01 180 bottom
C606  CSC0402_DY  [CSC_100X050X040_2]  81.91 20.8 90 bottom
C607  CSC0402_DY  [CSC_100X050X040_2]  73.94 21.77 90 bottom
C608  CSC0402_DY  [CSC_100X050X040_2]  73 20.9 270 bottom
C609  CSC0402_DY  [CSC_100X050X040_2]  73 22.63 90 bottom
C610  CSC0402_DY  [CSC_100X050X040_2]  81.91 19.18 270 bottom
C611  CSC0402_DY  [CSC_100X050X040_2]  81.91 22.43 90 bottom
C900  4.7uF_6.3V_3  [CSC_160X080X080_2]  20.24 23.6 90 bottom
C901  1uF_6.3V_2  [CSC_100X050X040_2]  15.08 18.03 270 bottom
C902  0.1uF_16V_2_DY  [CSC_100X050X040_2]  21.38 22.58 90 bottom
C903  0.1uF_16V_2  [CSC_100X050X040_2]  18.34 24.36 90 bottom
C904  1uF_6.3V_2  [CSC_100X050X040_2]  24.06 19.76 0 bottom
C905  4.7uF_6.3V_3  [CSC_160X080X080_2]  24.18 21.82 90 bottom
C906  0.1uF_16V_2  [CSC_100X050X040_2]  22.27 22.58 90 bottom
C907  6.8PF_50V_2_DY  [CSC_100X050X030_2]  22.63 13.89 0 bottom
C1301  10uF_6.3V_3  [CSC_160X080X080_2]  29 132.28 90 bottom
C1302  0.1uF_16V_2  [CSC_100X050X040_2]  29.11 134.29 90 bottom
C1303  10uF_6.3V_3  [CSC_160X080X080_2]  54.91 130.15 0 bottom
C1304  0.1uF_16V_2  [CSC_100X050X040_2]  55.29 131.29 0 bottom
C1305  CSC0402_DY  [CSC_100X050X040_2]  48.28 132.89 180 top
C1306  CSC0402_DY  [CSC_100X050X040_2]  56.44 127.48 0 bottom
C1307  CSC0402_DY  [CSC_100X050X040_2]  57.32 126.21 90 bottom
C2000  22uF_6.3V_5_DY  [CSC_200X125X130_2]  106.37 98.42 270 bottom
C2001  2.2uF_6.3V_3  [CSC_160X080X090_2]  107.77 98.42 270 bottom
C2002  22uF_6.3V_5  [CSC_200X125X130_2]  115.06 101.02 0 bottom
C2003  0.1uF_16V_2  [CSC_100X050X040_2]  116.23 99.72 0 bottom
C2004  CSC0402_DY  [CSC_100X050X040_2]  109.75 101.96 180 bottom
C2005  100uF_6.3V_DY  [CSTJB2_362X305X190_2]  100.53 93.6 180 bottom
C2007  22uF_6.3V_5  [CSC_200X125X130_2]  31.4 150.09 0 top
C2426  22uF_6.3V_5  [CSC_200X125X130_2]  19.68 116.38 270 bottom
C2427  0.1uF_16V_2  [CSC_100X050X040_2]  17.44 116.08 270 bottom
C2428  100uF_6.3V_DY  [CSTJB2_362X305X190_2]  22.98 116.41 0 bottom
C2432  1000PF_50V_2  [CSC_100X050X055_2]  18.4 116.08 270 bottom
C2440  0.1uF_16V_2  [CSC_100X050X040_2]  24.82 113.24 180 bottom
C2441  0.1uF_16V_2  [CSC_100X050X040_2]  24.82 114.18 180 bottom
C2456  2.2uF_6.3V_3  [CSC_160X080X090_2]  25.88 117.98 270 bottom
C2457  47uF_6.3V_5_DY  [CSC_200X125X130_2]  27.28 117.86 270 bottom
C2460  0.1uF_16V_2  [CSC_100X050X040_2]  27.61 149.86 270 top
C2461  1000PF_50V_2  [CSC_100X050X055_2]  28.88 149.86 270 top
C2462  0.1uF_16V_2  [CSC_100X050X040_2]  32.11 151.56 0 top
C3000  0.01uF_50V_2  [CSC_100X050X040_2]  55.29 141.71 180 bottom
C3001  0.1uF_16V_2  [CSC_100X050X040_2]  61.01 143.23 180 bottom
C3002  10uF_6.3V_3  [CSC_160X080X080_2]  60.5 139.8 180 bottom
C3003  680pF_50V_2  [CSC_100X050X040_2]  59.36 143.23 0 bottom
C3007  CSC0402_DY  [CSC_100X050X040_2]  114.86 152.24 270 top
C3008  1000PF_50V_2  [CSC_100X050X055_2]  61.44 132.33 180 bottom
C3009  0.1uF_16V_2_DY  [CSC_100X050X040_2]  81.76 138.1 0 top
C3010  0.1uF_16V_2  [CSC_100X050X040_2]  69.77 149.07 90 bottom
C3011  0.1uF_16V_2  [CSC_100X050X040_2]  68.88 149.07 90 bottom
C3014  0.1uF_16V_2  [CSC_100X050X040_2]  98.21 151.11 0 top
C3015  0.047uF_16V_2_DY  [CSC_100X050X040_2]  97.53 152.12 0 top
C3016  CSC0402_DY  [CSC_100X050X040_2]  97.69 153.95 270 top
C3019  4.7uF_25V_3  [CSC_160X080X095_2]  81.91 149.55 180 bottom
C3020  0.1uF_25V_2  [CSC_100X050X040_2]  81.51 150.6 180 bottom
C3150  100pF_50V_2  [CSC_100X050X040_2]  21.79 136.35 0 bottom
C3151  22pF_50V_2_DY  [CSC_100X050X040_2]  15.74 140.08 90 top
C3160  0.1uF_16V_2  [CSC_100X050X040_2]  19.38 127.08 180 top
C3161  0.1uF_16V_2  [CSC_100X050X040_2]  19.38 126.16 180 top
C3162  0.1uF_16V_2  [CSC_100X050X040_2]  20.29 129.84 180 top
C3163  0.1uF_16V_2  [CSC_100X050X040_2]  20.29 128.93 180 top
C3164  0.1uF_16V_2  [CSC_100X050X040_2]  19.38 132.61 180 top
C3165  0.1uF_16V_2  [CSC_100X050X040_2]  19.38 131.7 180 top
C3166  0.1uF_16V_2  [CSC_100X050X040_2]  20.27 135.36 180 top
C3167  0.1uF_16V_2  [CSC_100X050X040_2]  20.27 134.44 180 top
C3500  4.7uF_6.3V_3_DY  [CSC_160X080X080_2]  116.51 121.77 0 bottom
C3501  0.1uF_16V_2_DY  [CSC_100X050X040_2]  105.84 122.91 180 bottom
C3502  0.1uF_16V_2_DY  [CSC_100X050X040_2]  116.25 122.91 0 bottom
C3503  0.1uF_16V_2_DY  [CSC_100X050X040_2]  105.84 126.85 180 bottom
C3504  0.1uF_16V_2_DY  [CSC_100X050X040_2]  116.38 126.21 0 bottom
C3505  4.7uF_6.3V_3_DY  [CSC_160X080X080_2]  116.51 127.36 0 bottom
C3950  2.2uF_6.3V_2  [CSC_100X050X040_2]  111.14 33.3 0 bottom
C3951  2.2uF_6.3V_2  [CSC_100X050X040_2]  111.14 34.19 0 bottom
C3952  0.1uF_16V_2  [CSC_100X050X040_2]  99.23 35.28 270 top
C3953  0.1uF_16V_2  [CSC_100X050X040_2]  110.69 35.46 90 bottom
C3954  2.2uF_6.3V_2  [CSC_100X050X040_2]  103.58 34.62 0 top
C3955  2.2uF_6.3V_2  [CSC_100X050X040_2]  101.55 38.1 90 top
C3956  0.1uF_16V_2  [CSC_100X050X040_2]  99.92 41.53 270 top
C3957  0.1uF_16V_2  [CSC_100X050X040_2]  102.33 33.86 270 top
C3958  CSC0402_DY  [CSC_100X050X040_2]  102.21 39.78 180 top
C3959  0.1uF_16V_2  [CSC_100X050X040_2]  99.49 43.54 90 bottom
C3960  12pF_50V_2  [CSC_100X050X040_2]  103.83 39.78 0 top
C4100  0.22uF_6.3V_2  [CSC_100X050X040_2]  37.02 47.39 180 top
C4101  0.22uF_6.3V_2  [CSC_100X050X040_2]  34.66 47.2 0 top
C4102  0.1uF_16V_2  [CSC_100X050X040_2]  49.56 97.51 270 top
C4103  0.1uF_16V_2  [CSC_100X050X040_2]  59.24 107.94 270 top
C4104  0.22uF_6.3V_2  [CSC_100X050X040_2]  67.48 112.76 90 top
C4105  0.22uF_6.3V_2  [CSC_100X050X040_2]  66.23 107.06 180 top
C4106  0.22uF_6.3V_2  [CSC_100X050X040_2]  59.15 110.18 180 top
C4107  0.22uF_6.3V_2  [CSC_100X050X040_2]  40.39 52.62 270 top
C4108  0.22uF_6.3V_2  [CSC_100X050X040_2]  52.35 110.32 180 top
C4109  0.22uF_6.3V_2  [CSC_100X050X040_2]  46.81 116.79 90 top
C4110  0.1uF_16V_2  [CSC_100X050X040_2]  65.32 114.93 90 top
C4111  0.1uF_16V_2  [CSC_100X050X040_2]  53.46 112.71 0 top
C4112  0.1uF_16V_2  [CSC_100X050X040_2]  45.76 110.13 270 top
C4113  0.1uF_16V_2  [CSC_100X050X040_2]  34.89 83.55 180 top
C4114  0.1uF_16V_2  [CSC_100X050X040_2]  36.76 95.37 0 top
C4115  0.1uF_16V_2  [CSC_100X050X040_2]  31.13 91.69 90 top
C4116  0.1uF_16V_2  [CSC_100X050X040_2]  31.81 105.53 90 top
C4117  0.22uF_6.3V_2  [CSC_100X050X040_2]  47.11 112.02 270 top
C4118  0.22uF_6.3V_2  [CSC_100X050X040_2]  67.68 110.24 270 top
C4119  0.22uF_6.3V_2  [CSC_100X050X040_2]  66.21 116.8 90 top
C4120  0.22uF_6.3V_2  [CSC_100X050X040_2]  58.89 114.56 0 top
C4121  0.22uF_6.3V_2  [CSC_100X050X040_2]  61.05 107.32 90 top
C4122  0.22uF_6.3V_2  [CSC_100X050X040_2]  52.8 106.92 180 top
C4123  0.22uF_6.3V_2  [CSC_100X050X040_2]  55.41 105.22 270 top
C4124  0.22uF_6.3V_2  [CSC_100X050X040_2]  46.65 110.4 270 top
C4125  0.22uF_6.3V_2  [CSC_100X050X040_2]  52.8 107.81 180 top
C4126  0.22uF_6.3V_2  [CSC_100X050X040_2]  59.17 117 0 top
C4127  0.22uF_6.3V_2  [CSC_100X050X040_2]  66.21 114.92 90 top
C4128  0.22uF_6.3V_2  [CSC_100X050X040_2]  58.99 113.03 180 top
C4129  0.22uF_6.3V_2  [CSC_100X050X040_2]  65.67 105.3 0 top
C4130  0.22uF_6.3V_2  [CSC_100X050X040_2]  45.46 107.58 270 top
C4131  0.22uF_6.3V_2  [CSC_100X050X040_2]  46.24 113.9 180 top
C4132  180pF_50V_2  [CSC_100X050X055_2]  70.16 115.19 90 bottom
C4133  0.22uF_6.3V_2  [CSC_100X050X040_2]  30.37 105.38 90 top
C4134  0.22uF_6.3V_2  [CSC_100X050X040_2]  30.62 97.02 90 top
C4135  0.22uF_6.3V_2  [CSC_100X050X040_2]  37.83 98.05 180 top
C4136  0.22uF_6.3V_2  [CSC_100X050X040_2]  34.81 97.72 270 top
C4137  0.22uF_6.3V_2  [CSC_100X050X040_2]  33.54 91.34 270 top
C4138  0.22uF_6.3V_2  [CSC_100X050X040_2]  33.47 104.12 270 top
C4139  0.22uF_6.3V_2  [CSC_100X050X040_2]  39.17 98.17 270 top
C4140  0.22uF_6.3V_2  [CSC_100X050X040_2]  26.74 104.98 270 top
C4141  0.22uF_6.3V_2  [CSC_100X050X040_2]  28.26 98.04 90 top
C4142  0.22uF_6.3V_2  [CSC_100X050X040_2]  39.83 105.14 0 top
C4143  0.22uF_6.3V_2  [CSC_100X050X040_2]  49.28 99.05 0 top
C4144  0.22uF_6.3V_2  [CSC_100X050X040_2]  40.3 60.73 180 top
C4145  0.22uF_6.3V_2  [CSC_100X050X040_2]  24.81 84.86 90 top
C4146  0.22uF_6.3V_2  [CSC_100X050X040_2]  38.91 93.23 0 top
C4147  0.22uF_6.3V_2  [CSC_100X050X040_2]  38.09 91.52 270 top
C4148  0.22uF_6.3V_2  [CSC_100X050X040_2]  36.49 91.38 90 top
C4149  0.22uF_6.3V_2  [CSC_100X050X040_2]  39.47 91.53 0 top
C4150  0.22uF_6.3V_2  [CSC_100X050X040_2]  40.81 103.47 90 top
C4151  0.22uF_6.3V_2  [CSC_100X050X040_2]  49.21 100.3 0 top
C4152  0.22uF_6.3V_2  [CSC_100X050X040_2]  27.85 92.18 270 top
C4153  0.22uF_6.3V_2  [CSC_100X050X040_2]  36.33 104.38 180 top
C4154  0.22uF_6.3V_2  [CSC_100X050X040_2]  31.54 84.53 270 top
C4155  0.22uF_6.3V_2  [CSC_100X050X040_2]  33.14 84.01 0 top
C4156  180pF_50V_2  [CSC_100X050X055_2]  25.2 105.15 270 bottom
C4157  0.22uF_6.3V_2  [CSC_100X050X040_2]  29.23 92.18 270 top
C4158  0.22uF_6.3V_2  [CSC_100X050X040_2]  45.68 105.96 90 top
C4159  0.22uF_6.3V_2  [CSC_100X050X040_2]  35.11 111.18 180 top
C4160  0.22uF_6.3V_2  [CSC_100X050X040_2]  34.66 46.31 0 top
C4163  0.1uF_10V_2  [CSC_100X050X040_2]  47.65 43.79 180 top
C4164  0.1uF_10V_2  [CSC_100X050X040_2]  58 54.36 270 top
C4165  0.1uF_10V_2  [CSC_100X050X040_2]  47.65 42.01 180 top
C4166  0.1uF_10V_2  [CSC_100X050X040_2]  59.69 41.1 0 top
C4167  0.1uF_10V_2  [CSC_100X050X040_2]  68.04 51.9 0 top
C4168  0.22uF_6.3V_2  [CSC_100X050X040_2]  47.63 58.37 180 top
C4169  0.1uF_10V_2  [CSC_100X050X040_2]  68.04 53.68 0 top
C4170  0.22uF_6.3V_2  [CSC_100X050X040_2]  53.4 56.13 0 top
C4171  0.22uF_6.3V_2  [CSC_100X050X040_2]  46.03 42.75 0 top
C4172  0.22uF_6.3V_2  [CSC_100X050X040_2]  48.34 53.64 90 top
C4173  0.22uF_6.3V_2  [CSC_100X050X040_2]  31.9 65.46 0 top
C4174  0.22uF_6.3V_2  [CSC_100X050X040_2]  53.14 44.57 180 top
C4175  0.22uF_6.3V_2  [CSC_100X050X040_2]  38.31 57.81 270 top
C4176  0.22uF_6.3V_2  [CSC_100X050X040_2]  47.07 54.48 0 top
C4177  0.22uF_6.3V_2  [CSC_100X050X040_2]  53.53 46.99 180 top
C4178  0.22uF_6.3V_2  [CSC_100X050X040_2]  46.64 46.88 270 top
C4179  0.22uF_6.3V_2  [CSC_100X050X040_2]  64.77 55.19 90 top
C4180  0.22uF_6.3V_2  [CSC_100X050X040_2]  67.14 48.15 270 top
C4181  0.22uF_6.3V_2  [CSC_100X050X040_2]  67.14 44.9 270 top
C4182  0.22uF_6.3V_2  [CSC_100X050X040_2]  59.47 57.63 180 top
C4183  0.22uF_6.3V_2  [CSC_100X050X040_2]  58.33 45.08 270 top
C4184  0.22uF_6.3V_2  [CSC_100X050X040_2]  60.26 52.83 180 top
C4185  0.22uF_6.3V_2  [CSC_100X050X040_2]  59.72 49.93 0 top
C4186  0.22uF_6.3V_2  [CSC_100X050X040_2]  45.5 50.67 180 top
C4187  0.22uF_6.3V_2  [CSC_100X050X040_2]  67.14 46.53 270 top
C4188  0.22uF_6.3V_2  [CSC_100X050X040_2]  65.62 50.72 0 top
C4189  180pF_50V_2  [CSC_100X050X055_2]  65.59 44.83 270 top
C4190  0.1uF_10V_2  [CSC_100X050X040_2]  26.36 75.7 90 top
C4191  0.1uF_10V_2  [CSC_100X050X040_2]  33.39 69.48 180 top
C4192  0.1uF_10V_2  [CSC_100X050X040_2]  23.18 63.79 180 top
C4193  0.1uF_10V_2  [CSC_100X050X040_2]  33.75 58.05 180 top
C4194  0.22uF_6.3V_2  [CSC_100X050X040_2]  26.32 57.17 270 top
C4195  0.22uF_6.3V_2  [CSC_100X050X040_2]  31.15 57.86 90 top
C4196  0.22uF_6.3V_2  [CSC_100X050X040_2]  39.6 69.16 180 top
C4197  0.22uF_6.3V_2  [CSC_100X050X040_2]  36.84 56.94 90 top
C4198  0.22uF_6.3V_2  [CSC_100X050X040_2]  29.17 78.41 90 top
C4199  0.22uF_6.3V_2  [CSC_100X050X040_2]  32.49 57.88 90 top
C4200  0.1uF_10V_2  [CSC_100X050X040_2]  44.47 67.03 0 top
C4201  0.22uF_6.3V_2  [CSC_100X050X040_2]  38.54 83.77 270 top
C4202  0.22uF_6.3V_2  [CSC_100X050X040_2]  36.08 84.98 180 top
C4203  0.22uF_6.3V_2  [CSC_100X050X040_2]  27.69 78.1 90 top
C4204  0.22uF_6.3V_2  [CSC_100X050X040_2]  40.23 70.54 180 top
C4205  0.22uF_6.3V_2  [CSC_100X050X040_2]  37.68 69.57 0 top
C4206  0.22uF_6.3V_2  [CSC_100X050X040_2]  33.59 63.93 270 top
C4207  0.22uF_6.3V_2  [CSC_100X050X040_2]  30.51 65.1 270 top
C4208  0.22uF_6.3V_2  [CSC_100X050X040_2]  36.75 60.86 270 top
C4209  0.22uF_6.3V_2  [CSC_100X050X040_2]  35.51 63.93 270 top
C4210  0.22uF_6.3V_2  [CSC_100X050X040_2]  33.46 76.73 270 top
C4211  0.22uF_6.3V_2  [CSC_100X050X040_2]  35.01 57.13 270 top
C4212  0.22uF_6.3V_2  [CSC_100X050X040_2]  32.09 69.8 270 top
C4213  0.22uF_6.3V_2  [CSC_100X050X040_2]  34.27 70.75 270 top
C4214  0.22uF_6.3V_2  [CSC_100X050X040_2]  36.71 83.74 270 top
C4215  180pF_50V_2  [CSC_100X050X055_2]  24.99 56.57 270 bottom
C4251  0.1uF_16V_2  [CSC_100X050X040_2]  70.2 116.7 180 top
C4252  0.1uF_16V_2  [CSC_100X050X040_2]  68.13 114.92 0 top
C4441  0.1uF_16V_2  [CSC_100X050X040_2]  77.9 113.36 180 bottom
C4504  0.1uF_16V_2  [CSC_100X050X040_2]  80.95 82.31 0 bottom
C4505  0.1uF_16V_2  [CSC_100X050X040_2]  80.95 83.33 0 bottom
C4506  0.1uF_16V_2_DY  [CSC_100X050X040_2]  106.25 47.04 0 bottom
C4507  0.1uF_16V_2_DY  [CSC_100X050X040_2]  106.85 52.63 180 bottom
C4509  12pF_50V_2  [CSC_100X050X040_2]  85.16 75.87 270 bottom
C4510  12pF_50V_2  [CSC_100X050X040_2]  85.16 74.22 90 bottom
C4511  15pF_50V_2  [CSC_100X050X040_2]  87.14 72.21 0 bottom
C4512  15pF_50V_2  [CSC_100X050X040_2]  85.52 72.21 180 bottom
C4513  0.1uF_16V_2  [CSC_100X050X040_2]  77.24 74.68 0 top
C4514  1uF_10V_2  [CSC_100X050X040_2]  76.93 73.51 0 top
C4515  0.1uF_16V_2_DY  [CSC_100X050X040_2]  65.83 64.95 90 bottom
C4516  22uF_6.3V_5  [CSC_200X125X130_2]  88.67 101.7 90 bottom
C4517  2.2uF_6.3V_2  [CSC_100X050X040_2]  62.43 84.1 270 top
C4518  2.2uF_6.3V_2  [CSC_100X050X040_2]  64.03 88.23 90 top
C4519  2.2uF_6.3V_2  [CSC_100X050X040_2]  65.1 84.73 0 top
C4520  2.2uF_6.3V_2  [CSC_100X050X040_2]  62.09 80.12 180 top
C4521  2.2uF_6.3V_2  [CSC_100X050X040_2]  64.1 79.74 270 top
C4522  2.2uF_6.3V_2  [CSC_100X050X040_2]  65 79.74 270 top
C4523  2.2uF_6.3V_2  [CSC_100X050X040_2]  63.95 82.06 90 top
C4524  2.2uF_6.3V_2  [CSC_100X050X040_2]  62.45 81.36 90 top
C4525  22uF_6.3V_5  [CSC_200X125X130_2]  88.69 50.35 270 bottom
C4526  22uF_6.3V_5  [CSC_200X125X130_2]  90.31 50.35 270 bottom
C4527  2.2uF_6.3V_2  [CSC_100X050X040_2]  65.86 76.1 0 top
C4528  2.2uF_6.3V_2  [CSC_100X050X040_2]  65.86 76.98 0 top
C4529  2.2uF_6.3V_2  [CSC_100X050X040_2]  65.86 77.87 0 top
C4530  2.2uF_6.3V_2  [CSC_100X050X040_2]  64.08 78.12 90 top
C4531  2.2uF_6.3V_2  [CSC_100X050X040_2]  63.77 75.66 180 top
C4532  1uF_6.3V_2  [CSC_100X050X040_2]  62.53 82.61 180 top
C4533  1uF_6.3V_2  [CSC_100X050X040_2]  73.83 118.34 180 bottom
C4534  1uF_6.3V_2  [CSC_100X050X040_2]  73.83 119.23 180 bottom
C4535  1uF_6.3V_2  [CSC_100X050X040_2]  61.67 86.64 270 top
C4536  1uF_6.3V_2  [CSC_100X050X040_2]  63.19 86 270 top
C4537  1uF_6.3V_2  [CSC_100X050X040_2]  73.83 117.45 180 bottom
C4538  1uF_6.3V_2  [CSC_100X050X040_2]  62.83 79.23 180 top
C4539  1uF_6.3V_2  [CSC_100X050X040_2]  61.59 77.4 270 top
C4540  1uF_6.3V_2  [CSC_100X050X040_2]  73.83 116.56 180 bottom
C4541  1uF_6.3V_2  [CSC_100X050X040_2]  69.05 80.13 0 top
C4542  1uF_6.3V_2  [CSC_100X050X040_2]  72.13 82.02 90 top
C4543  1uF_6.3V_2  [CSC_100X050X040_2]  68.02 76.48 270 top
C4544  1uF_6.3V_2  [CSC_100X050X040_2]  68.27 78.76 0 top
C4545  1uF_6.3V_2  [CSC_100X050X040_2]  67.13 76.48 270 top
C4546  22UF_6.3V_3  [CSC_160X080X090_2]  104.19 97 0 bottom
C4547  22UF_6.3V_3  [CSC_160X080X090_2]  104.19 98.15 0 bottom
C4548  1uF_6.3V_2  [CSC_100X050X040_2]  70.52 77.76 0 top
C4549  1uF_6.3V_2  [CSC_100X050X040_2]  67.56 84.1 180 top
C4550  1uF_6.3V_2  [CSC_100X050X040_2]  67.56 84.99 180 top
C4551  1uF_6.3V_2  [CSC_100X050X040_2]  70.56 85.62 0 top
C4552  1uF_6.3V_2  [CSC_100X050X040_2]  70.56 84.73 0 top
C4553  1uF_6.3V_2  [CSC_100X050X040_2]  68.27 77.83 0 top
C4554  22UF_6.3V_3  [CSC_160X080X090_2]  104.19 99.29 0 bottom
C4555  2.2uF_6.3V_2  [CSC_100X050X040_2]  73.83 77.42 90 top
C4556  1uF_6.3V_2  [CSC_100X050X040_2]  71.22 80.4 270 top
C4557  1uF_6.3V_2  [CSC_100X050X040_2]  70.31 80.39 270 top
C4558  1uF_6.3V_2  [CSC_100X050X040_2]  70.56 81.66 0 top
C4559  1uF_6.3V_2  [CSC_100X050X040_2]  71.09 76.52 90 top
C4560  1uF_6.3V_2  [CSC_100X050X040_2]  70.56 82.55 0 top
C4561  1uF_6.3V_2  [CSC_100X050X040_2]  72.95 77.42 90 top
C4562  1uF_6.3V_2  [CSC_100X050X040_2]  72.06 77.42 90 top
C4563  1uF_6.3V_2  [CSC_100X050X040_2]  72.12 80.4 270 top
C4564  22uF_6.3V_5  [CSC_200X125X130_2]  100.76 97.38 180 bottom
C4565  22uF_6.3V_5  [CSC_200X125X130_2]  88.29 64.54 90 bottom
C4566  2.2uF_6.3V_2  [CSC_100X050X040_2]  60.46 79.54 0 top
C4569  1uF_6.3V_2  [CSC_100X050X040_2]  61.54 85.03 90 top
C4570  1uF_6.3V_2  [CSC_100X050X040_2]  75.03 72.36 270 top
C4571  1uF_6.3V_2  [CSC_100X050X040_2]  59.72 77.49 0 top
C4572  22UF_6.3V_3  [CSC_160X080X090_2]  51.57 98.94 135 bottom
C4573  1uF_6.3V_2  [CSC_100X050X040_2]  60.6 83.36 0 top
C4574  22UF_6.3V_3  [CSC_160X080X090_2]  48.68 62.77 315 bottom
C4575  22UF_6.3V_3  [CSC_160X080X090_2]  49.98 97.34 135 bottom
C4576  22UF_6.3V_3  [CSC_160X080X090_2]  50.78 98.15 135 bottom
C4577  22UF_6.3V_3  [CSC_160X080X090_2]  50.96 65.07 315 bottom
C4578  22UF_6.3V_3  [CSC_160X080X090_2]  49.83 63.92 315 bottom
C4579  1uF_6.3V_2  [CSC_100X050X040_2]  79.19 65.3 0 bottom
C4580  1uF_6.3V_2  [CSC_100X050X040_2]  76.73 65.3 180 bottom
C4581  1uF_6.3V_2  [CSC_100X050X040_2]  75.71 67.64 90 top
C4582  1uF_6.3V_2  [CSC_100X050X040_2]  63.65 68.51 180 top
C4583  1uF_6.3V_2  [CSC_100X050X040_2]  67.51 73.51 270 top
C4584  1uF_6.3V_2  [CSC_100X050X040_2]  68.7 74.77 180 top
C4585  1uF_6.3V_2  [CSC_100X050X040_2]  69.59 76.48 90 top
C4586  1uF_6.3V_2  [CSC_100X050X040_2]  63.18 76.91 270 top
C4587  1uF_6.3V_2  [CSC_100X050X040_2]  60.17 68.96 180 top
C4588  1uF_6.3V_2  [CSC_100X050X040_2]  72.64 86.75 270 top
C4589  1uF_6.3V_2  [CSC_100X050X040_2]  71.47 89.41 90 top
C4590  1uF_6.3V_2  [CSC_100X050X040_2]  73.33 88.11 0 top
C4591  1uF_6.3V_2  [CSC_100X050X040_2]  70.58 89.41 90 top
C4592  1uF_6.3V_2  [CSC_100X050X040_2]  69.39 88.14 180 top
C4593  1uF_6.3V_2  [CSC_100X050X040_2]  70.56 83.84 0 top
C4594  1uF_6.3V_2  [CSC_100X050X040_2]  67.5 86.17 0 top
C4595  1uF_6.3V_2  [CSC_100X050X040_2]  70.56 86.51 0 top
C4596  1uF_6.3V_2  [CSC_100X050X040_2]  67.48 87.48 180 top
C4597  1uF_6.3V_2  [CSC_100X050X040_2]  67.84 88.72 90 top
C4598  1uF_6.3V_2  [CSC_100X050X040_2]  74.12 90.05 270 top
C4599  1uF_6.3V_2  [CSC_100X050X040_2]  69.67 89.41 90 top
C4600  1uF_6.3V_2  [CSC_100X050X040_2]  68.35 82.29 0 top
C4601  1uF_6.3V_2  [CSC_100X050X040_2]  68.31 83.19 0 top
C4602  1uF_6.3V_2  [CSC_100X050X040_2]  80.59 81.03 90 bottom
C4603  1uF_6.3V_2  [CSC_100X050X040_2]  77.01 70.46 270 top
C4604  1uF_6.3V_2  [CSC_100X050X040_2]  75.74 68.88 180 top
C4605  1uF_6.3V_2  [CSC_100X050X040_2]  66.23 83.44 90 top
C4606  1uF_6.3V_2  [CSC_100X050X040_2]  74.14 72.36 270 top
C4607  1uF_6.3V_2  [CSC_100X050X040_2]  81.51 81.03 90 bottom
C4608  1uF_6.3V_2  [CSC_100X050X040_2]  77.9 70.46 270 top
C4609  22uF_6.3V_5  [CSC_200X125X130_2]  87.04 101.7 90 bottom
C4610  0.1uF_10V_2_DY  [CSC_100X050X040_2]  53.81 74.15 180 top
C4611  0.1uF_16V_2  [CSC_100X050X040_2]  75.49 149.28 270 bottom
C4612  0.1uF_16V_2  [CSC_100X050X040_2]  74.6 149.28 270 bottom
C4613  0.1uF_16V_2  [CSC_100X050X040_2]  73.68 149.48 270 bottom
C4614  0.1uF_16V_2  [CSC_100X050X040_2]  72.77 149.48 270 bottom
C4616  0.2pF_50V_2  [CSC_100X050X055_2]  47.03 97.37 90 top
C4617  0.1uF_10V_2_DY  [CSC_100X050X040_2]  53.77 90.2 180 top
C4623  0.2pF_50V_2  [CSC_100X050X055_2]  44.51 64.46 180 top
C4625  1uF_10V_2  [CSC_100X050X040_2]  78.25 72.62 180 top
C4626  1uF_6.3V_2  [CSC_100X050X040_2]  68.82 85.8 90 top
C4627  CSC0805_DY  [CSC_200X125X130_2]  80.92 76.3 90 bottom
C4630  22uF_6.3V_5  [CSC_200X125X130_2]  100.76 99.03 180 bottom
C4631  0.1uF_16V_2  [CSC_100X050X040_2]  108.76 59.05 180 bottom
C4636  0.1uF_16V_2  [CSC_100X050X040_2]  108.12 53.57 0 bottom
C4640  22UF_6.3V_3  [CSC_160X080X090_2]  90.27 63.65 0 bottom
C4652  CSC0402_DY  [CSC_100X050X040_2]  68.35 66.37 90 top
C6000  10UF_25V_5  [CSC_200X125X140_2]  69.45 30.83 90 bottom
C6001  4.7uF_25V_5  [CSC_200X125X130_2]  71.11 30.83 90 bottom
C6010  10UF_25V_5  [CSC_200X125X140_2]  88.49 26.95 0 bottom
C6011  4.7uF_25V_5  [CSC_200X125X130_2]  83.33 29.95 90 bottom
C6020  0.1uF_16V_2  [CSC_100X050X040_2]  59.33 25.4 270 bottom
C6021  0.1uF_25V_3  [CSC_160X080X080_2]  56.84 25.04 180 bottom
C6022  0.1uF_25V_3  [CSC_160X080X080_2]  56.84 23.9 180 bottom
C6023  0.1uF_16V_2  [CSC_100X050X040_2]  66.05 27.64 90 bottom
C6024  0.1uF_25V_3  [CSC_160X080X080_2]  67.69 26.9 270 bottom
C6025  0.1uF_25V_3  [CSC_160X080X080_2]  67.69 29.23 90 bottom
C6026  1uF_25V_3  [CSC_160X080X080_2]  60.42 22.71 90 bottom
C6027  0.047uF_16V_2  [CSC_100X050X040_2]  62 22.02 90 bottom
C6028  1uF_10V_2  [CSC_100X050X040_2]  64.74 24.26 270 bottom
C6030  470pF_50V_2  [CSC_100X050X040_2]  53.13 20.29 0 top
C6031  0.1uF_25V_3  [CSC_160X080X080_2]  55.98 19.68 0 top
C6032  0.1uF_16V_2  [CSC_100X050X040_2]  64 29.95 90 bottom
C6033  0.1uF_25V_3_DY  [CSC_160X080X080_2]  86.46 30.25 180 bottom
C6036  100pF_50V_2  [CSC_100X050X040_2]  61.82 30.33 0 bottom
C6037  100pF_50V_2  [CSC_100X050X040_2]  70.25 163.83 180 top
C6050  1000PF_50V_2  [CSC_100X050X055_2]  89.71 28.24 0 bottom
C6051  1uF_10V_2  [CSC_100X050X040_2]  91.77 28.47 0 bottom
C6100  100uF_6.3V  [CS_730X430X210_2]  78.03 133.32 90 bottom
C6109  0.1uF_16V_2  [CSC_100X050X040_2]  76.98 138.38 0 bottom
C6110  10UF_25V_5  [CSC_200X125X140_2]  73.71 144.5 0 bottom
C6111  4.7uF_25V_5  [CSC_200X125X130_2]  73.71 142.85 0 bottom
C6115  0.1uF_16V_2  [CSC_100X050X040_2]  70.91 138.4 0 bottom
C6121  10uF_6.3V_3  [CSC_160X080X080_2]  77.9 139.42 0 bottom
C6122  1uF_6.3V_2  [CSC_100X050X040_2]  70.91 141.71 180 bottom
C6150  100uF_6.3V  [CS_730X430X210_2]  98.22 133.71 90 bottom
C6160  10UF_25V_5  [CSC_200X125X140_2]  93.14 144.5 0 bottom
C6161  10UF_25V_5  [CSC_200X125X140_2]  93.14 142.85 0 bottom
C6162  10UF_25V_5_DY  [CSC_200X125X140_2]  84.25 145.21 180 bottom
C6165  0.1uF_16V_2  [CSC_100X050X040_2]  88.44 136.68 270 bottom
C6166  CSC0402_DY  [CSC_100X050X040_2]  87.55 141.58 0 bottom
C6169  0.1uF_16V_2  [CSC_100X050X040_2]  96.19 139.17 0 bottom
C6172  1uF_6.3V_2  [CSC_100X050X040_2]  89.35 139.95 180 bottom
C6600  22uF_6.3V_5  [CSC_200X125X130_2]  93.72 87.98 0 bottom
C6601  22uF_6.3V_5  [CSC_200X125X130_2]  93.72 89.59 0 bottom
C6602  22uF_6.3V_5  [CSC_200X125X130_2]  93.72 91.19 0 bottom
C6603  22uF_6.3V_5  [CSC_200X125X130_2]  93.72 86.36 0 bottom
C6604  22uF_6.3V_5  [CSC_200X125X130_2]  96.82 101.7 90 bottom
C6605  22uF_6.3V_5  [CSC_200X125X130_2]  95.17 101.7 90 bottom
C6606  22uF_6.3V_5  [CSC_200X125X130_2]  90.29 101.7 90 bottom
C6607  22uF_6.3V_5  [CSC_200X125X130_2]  91.92 101.7 90 bottom
C6608  22uF_6.3V_5  [CSC_200X125X130_2]  93.55 101.7 90 bottom
C6609  220uF_2V_10%  [CS_730X430X210_2]  92.96 94.36 0 bottom
C6610  10UF_25V_5  [CSC_200X125X140_2]  101.55 81.38 90 bottom
C6611  10UF_25V_5  [CSC_200X125X140_2]  99.89 81.38 90 bottom
C6612  0.1uF_25V_2  [CSC_100X050X040_2]  94.66 77.67 270 bottom
C6613  330pF_50V_2  [CSC_100X050X040_2]  89.4 68.53 270 bottom
C6614  10pF_50V_2  [CSC_100X050X040_2]  91.01 66.83 270 bottom
C6615  0.22uF_16V_2  [CSC_100X050X055_2]  99.21 71.58 90 bottom
C6616  1000PF_50V_2  [CSC_100X050X055_2]  96.34 66.01 0 bottom
C6617  4700pF_50V_2  [CSC_100X050X040_2]  90.12 66.83 270 bottom
C6618  1000PF_50V_2  [CSC_100X050X055_2]  91.18 70.79 270 bottom
C6639  CSC0402_DY  [CSC_100X050X040_2]  94.74 65.13 0 bottom
C6640  1.2pF_50V_2  [CSC_100X050X040_2]  94.74 66.01 0 bottom
C6642  1uF_6.3V_2  [CSC_100X050X040_2]  91.74 72.06 180 bottom
C6643  2.2uF_6.3V_3  [CSC_160X080X090_2]  99.21 66.73 0 bottom
C6645  470pF_50V_2  [CSC_100X050X040_2]  93.14 65.3 180 bottom
C6646  0.01uF_50V_2  [CSC_100X050X040_2]  99.56 68.63 0 bottom
C6647  0.01uF_50V_2  [CSC_100X050X040_2]  97.1 73.99 0 bottom
C6649  2200pF_50V_2  [CSC_100X050X040_2]  89.4 70.21 270 bottom
C6699  15uF_25V_DY  [CS_730X430X210_2_615]  78.13 34.95 180 bottom
C6700  22uF_6.3V_5  [CSC_200X125X130_2]  85.39 50.34 270 bottom
C6701  22uF_6.3V_5  [CSC_200X125X130_2]  87.04 50.34 270 bottom
C6702  220uF_2V_10%  [CS_730X430X210_2]  87.07 56.82 90 bottom
C6710  10UF_25V_5  [CSC_200X125X140_2]  92.33 43.74 90 bottom
C6711  10UF_25V_5  [CSC_200X125X140_2]  90.65 43.74 90 bottom
C6712  0.1uF_25V_2  [CSC_100X050X040_2]  85.32 40.33 180 bottom
C6713  330pF_50V_2  [CSC_100X050X040_2]  97.99 62.03 90 bottom
C6714  10pF_50V_2  [CSC_100X050X040_2]  95.81 60.65 180 bottom
C6715  0.22uF_16V_2  [CSC_100X050X055_2]  97.86 52.2 0 bottom
C6716  1000PF_50V_2  [CSC_100X050X055_2]  91.89 54.86 270 bottom
C6717  4700pF_50V_2  [CSC_100X050X040_2]  95.81 61.57 180 bottom
C6718  1000PF_50V_2  [CSC_100X050X055_2]  100.05 60.63 180 bottom
C6739  CSC0402_DY  [CSC_100X050X040_2]  91.77 57.35 270 bottom
C6740  1.2pF_50V_2  [CSC_100X050X040_2]  92.66 57.35 270 bottom
C6742  1uF_6.3V_2  [CSC_100X050X040_2]  99.69 59.23 90 bottom
C6743  2.2uF_6.3V_3  [CSC_160X080X090_2]  92.96 53.47 180 bottom
C6745  470pF_50V_2  [CSC_100X050X040_2]  93.04 58.95 90 bottom
C6746  0.01uF_50V_2  [CSC_100X050X040_2]  95.88 51.82 0 bottom
C6747  0.01uF_50V_2  [CSC_100X050X040_2]  100.78 53.62 0 bottom
C6749  2200pF_50V_2  [CSC_100X050X040_2]  99.26 61.54 180 bottom
C7000  10uF_6.3V_3  [CSC_160X080X080_2]  101.72 110.64 270 bottom
C7001  22uF_6.3V_5  [CSC_200X125X130_2]  100 110.13 270 bottom
C7002  10uF_6.3V_3  [CSC_160X080X080_2]  103.3 113.39 0 bottom
C7003  22uF_6.3V_5  [CSC_200X125X130_2]  103.76 112.01 0 bottom
C7100  220pF_50V_2  [CSC_100X050X040_2]  65.25 123.57 270 bottom
C7101  33pF_50V  [CSC_100X050X040_2]  88.06 125.96 180 bottom
C7102  10uF_6.3V_5  [CSC_200X125X130_2]  85.75 125.32 90 bottom
C7104  10uF_6.3V_3  [CSC_160X080X080_2]  67.74 123.42 180 bottom
C7108  10uF_6.3V_3  [CSC_160X080X080_2]  58.98 125.96 180 bottom
C7109  33pF_50V  [CSC_100X050X040_2]  64.36 123.57 270 bottom
C7110  1uF_10V_2  [CSC_100X050X040_2]  65.58 129.9 0 bottom
C7111  CSC0402_DY  [CSC_100X050X040_2]  65.38 129.08 0 top
C7114  1uF_10V_2  [CSC_100X050X040_2]  63.93 129.9 180 bottom
C7116  CSC0402_DY  [CSC_100X050X040_2]  102.66 126.97 0 bottom
C7120  1uF_10V_2  [CSC_100X050X040_2]  91.11 128.75 180 bottom
C7121  10uF_6.3V_3  [CSC_160X080X080_2]  88.31 131.93 90 bottom
C7122  680pF_50V_2  [CSC_100X050X040_2]  88.06 126.97 180 bottom
C7123  1uF_10V_2  [CSC_100X050X040_2]  91.11 124.31 180 bottom
C7125  CSC0402_DY  [CSC_100X050X040_2]  102.66 126.09 0 bottom
C7203  0.1uF_16V_2_DY  [CSC_100X050X040_2]  103.15 57.43 90 bottom
C7205  0.1uF_16V_2_DY  [CSC_100X050X040_2]  76.63 109.52 90 bottom
C7206  0.1uF_16V_2  [CSC_100X050X040_2]  35.99 33.5 270 bottom
C7207  CSC0402_DY  [CSC_100X050X040_2]  35.96 26.97 270 bottom
C7225  CSC0402_DY  [CSC_100X050X040_2]  101.72 55.8 270 bottom
C7510  0.1uF_25V_2  [CSC_100X050X040_2]  83.64 137.85 180 bottom
C7511  0.1uF_25V_2  [CSC_100X050X040_2]  87.27 135.69 0 top
C7512  0.1uF_25V_2  [CSC_100X050X040_2]  116.3 97 0 bottom
C7513  0.1uF_25V_2  [CSC_100X050X040_2]  105.15 45.29 270 bottom
C7514  0.1uF_16V_2  [CSC_100X050X040_2]  43.61 133.2 90 top
C7515  0.1uF_16V_2  [CSC_100X050X040_2]  81.53 84.64 0 top
C7516  0.1uF_16V_2  [CSC_100X050X040_2]  91.74 123.39 180 bottom
C7517  0.1uF_16V_2  [CSC_100X050X040_2]  85.39 117.7 270 bottom
C7518  0.1uF_16V_2  [CSC_100X050X040_2]  93.47 77.6 270 bottom
C7519  0.1uF_16V_2  [CSC_100X050X040_2]  83.64 68.55 90 top
C7520  0.1uF_16V_2  [CSC_100X050X040_2]  91.59 50.37 270 bottom
C7521  0.1uF_16V_2  [CSC_100X050X040_2]  101.01 133.61 90 bottom
C7522  0.1uF_16V_2  [CSC_100X050X040_2]  69.08 57.56 270 top
C7526  0.1uF_16V_2  [CSC_100X050X040_2]  57.86 144.17 0 bottom
C7527  0.1uF_16V_2  [CSC_100X050X040_2]  116.18 104.93 270 bottom
C7528  18pF_50V_2  [CSC_100X050X040_2]  59.69 42.01 0 top
C7529  18pF_50V_2  [CSC_100X050X040_2]  68.04 51.01 0 top
C7531  18pF_50V_2  [CSC_100X050X040_2]  65.6 47.35 90 top
C7532  18pF_50V_2  [CSC_100X050X040_2]  44.8 49.39 180 top
C7533  18pF_50V_2  [CSC_100X050X040_2]  58.89 54.36 270 top
C7534  18pF_50V_2  [CSC_100X050X040_2]  47.65 42.9 180 top
C7535  18pF_50V_2  [CSC_100X050X040_2]  23.18 62.87 180 top
C7536  18pF_50V_2  [CSC_100X050X040_2]  33.78 59 180 top
C7537  18pF_50V_2  [CSC_100X050X040_2]  34.62 63.93 270 top
C7538  18pF_50V_2  [CSC_100X050X040_2]  27.24 75.7 90 top
C7539  18pF_50V_2  [CSC_100X050X040_2]  33.39 68.59 180 top
C7540  18pF_50V_2  [CSC_100X050X040_2]  27.14 79.64 180 top
C7541  0.1uF_25V_2  [CSC_100X050X040_2]  92.68 29.74 90 bottom
C7546  0.1uF_25V_2  [CSC_100X050X040_2]  62.43 32.44 90 top
C7551  0.1uF_16V_2  [CSC_100X050X040_2]  76.35 105.52 180 top
C7552  0.1uF_16V_2  [CSC_100X050X040_2]  71.65 105.49 180 top
C7566  0.1uF_16V_2  [CSC_100X050X040_2]  68.07 125.15 90 top
C7567  0.1uF_16V_2  [CSC_100X050X040_2]  42.24 118.52 180 bottom
C7568  0.1uF_16V_2  [CSC_100X050X040_2]  25.93 53.31 180 bottom
C7569  0.1uF_16V_2  [CSC_100X050X040_2]  19.78 75.92 270 bottom
C7572  0.1uF_16V_2  [CSC_100X050X040_2]  43.25 114.4 270 top
C7573  0.1uF_16V_2  [CSC_100X050X040_2]  65.05 120.22 270 top
C7574  0.1uF_16V_2  [CSC_100X050X040_2]  24.74 48.44 270 top
C7577  0.1uF_25V_2  [CSC_100X050X040_2]  50.14 18.16 270 bottom
C7578  1000PF_50V_2  [CSC_100X050X055_2]  62.89 122.61 180 bottom
C7580  1000PF_50V_2  [CSC_100X050X055_2]  72.89 113.89 90 bottom
C7583  1000PF_50V_2  [CSC_100X050X055_2]  49.88 38.71 180 top
C7584  1000PF_50V_2  [CSC_100X050X055_2]  24.48 76.78 270 top
C7585  1000PF_50V_2  [CSC_100X050X055_2]  55.52 35.66 270 bottom
C7591  0.1uF_16V_2  [CSC_100X050X040_2]  90.9 53.97 270 bottom
C7593  0.1uF_16V_2  [CSC_100X050X040_2]  100.78 95.76 180 bottom
C7600  2200pF_50V_2  [CSC_100X050X040_2]  84.22 32.03 0 bottom
C7601  1000PF_50V_2  [CSC_100X050X055_2]  28.06 136.96 0 bottom
C7602  10pF_50V_2  [CSC_100X050X040_2]  28.06 137.9 0 bottom
C7604  470pF_50V_2  [CSC_100X050X040_2]  68.2 31.29 90 bottom
C7661  CSC0402_DY  [CSC_100X050X040_2]  91.36 76.63 90 bottom
C7761  CSC0402_DY  [CSC_100X050X040_2]  79.68 41.71 180 bottom
C7979  1000PF_50V_2  [CSC_100X050X055_2]  19.78 101.68 270 bottom
C9100  1uF_6.3V_2  [CSC_100X050X040_2]  68.75 4.75 270 bottom
C9101  1uF_6.3V_2  [CSC_100X050X040_2]  69.9 4.7 270 bottom
C9102  1000PF_50V_2_DY  [CSC_100X050X055_2]  71.56 6.05 270 bottom
C9150  1000PF_50V_2  [CSC_100X050X055_2]  51.07 3.39 0 top
C60013  0.1uF_25V_3  [CSC_160X080X080_2]  55.83 18.49 0 bottom
C60209  1uF_6.3V_2  [CSC_100X050X040_2]  102.54 115.04 270 bottom
C60300  22uF_6.3V_5  [CSC_200X125X130_2]  44.17 32.36 270 bottom
C60301  22uF_6.3V_5  [CSC_200X125X130_2]  42.49 32.36 270 bottom
C60302  22uF_6.3V_5  [CSC_200X125X130_2]  40.84 32.36 270 bottom
C60303  22uF_6.3V_5_DY  [CSC_200X125X130_2]  39.19 32.36 270 bottom
C60304  0.022uF_16V_2_DY  [CSC_100X050X040_2]  36.88 25.55 90 bottom
C60306  1uF_6.3V_2  [CSC_100X050X040_2]  37.41 29.69 90 bottom
C60310  10UF_25V_5  [CSC_200X125X140_2]  47.09 24.71 0 bottom
C60311  10UF_25V_5_DY  [CSC_200X125X140_2]  47.09 23.09 0 bottom
C60315  0.1uF_16V_2  [CSC_100X050X040_2]  44.98 22.2 270 bottom
C60316  CSC0402_DY  [CSC_100X050X040_2]  50.95 22.86 180 bottom
C60350  10uF_6.3V_3  [CSC_160X080X080_2]  42.11 22.33 0 bottom
C60351  0.1uF_16V_2  [CSC_100X050X040_2]  38.96 24.03 270 bottom
C60600  22uF_6.3V_5  [CSC_200X125X130_2]  89.07 121.01 180 bottom
C60601  22uF_6.3V_5  [CSC_200X125X130_2]  89.07 119.35 180 bottom
C60602  22uF_6.3V_5  [CSC_200X125X130_2]  89.07 117.7 180 bottom
C60603  22uF_6.3V_5  [CSC_200X125X130_2]  89.07 116.05 180 bottom
C60604  22uF_6.3V_5  [CSC_200X125X130_2]  89.07 114.4 180 bottom
C60610  10uF_6.3V_3  [CSC_160X080X080_2]  97.58 122.53 0 bottom
C60611  10uF_6.3V_3  [CSC_160X080X080_2]  97.58 121.39 0 bottom
C60612  10uF_6.3V_3  [CSC_160X080X080_2]  97.58 120.24 0 bottom
C60900  470uF_2V  [CS_730X430X190_2]  99.62 106.27 0 bottom
C60901  22uF_6.3V_5  [CSC_200X125X130_2]  100.12 102.46 270 bottom
C60910  10uF_6.3V_3  [CSC_160X080X080_2]  97.99 109.24 0 bottom
C60911  10uF_6.3V_3  [CSC_160X080X080_2]  97.99 110.39 0 bottom
C60912  10uF_6.3V_3  [CSC_160X080X080_2]  97.99 111.53 0 bottom
C61000  22uF_6.3V_5  [CSC_200X125X130_2]  100.76 122.66 90 bottom
C61010  10uF_6.3V_3  [CSC_160X080X080_2]  102.79 118.34 90 bottom
C61100  22uF_6.3V_5  [CSC_200X125X130_2]  103.04 120.37 0 bottom
C61110  10uF_6.3V_3  [CSC_160X080X080_2]  101.65 118.34 90 bottom
C61700  10uF_6.3V_3  [CSC_160X080X080_2]  103.68 115.42 270 bottom
C61710  10uF_6.3V_3  [CSC_160X080X080_2]  103.93 118.34 90 bottom
CN245  ACES_50503_0104N_001_10P  [FPC_ACES_10_100_R_200_3]  105.77 140.95 270 bottom
CN251  ACES_50503_0244N_001_24P  [FPC_ACES_24_100_R_200_4]  103.28 155.4 0 bottom
CN281  ACES_50503_0084N_001_8P  [FPC_ACES_8_100_R_200_4]  106.77 70.95 270 bottom
CN600  LCN_AWM10_0429980_0004_4P  [WTB_LCN_4_100_SMD_R_M_290]  77.88 17.17 180 bottom
CN901  TAITWUN_PSDATG_11GLBS1NN4H1_11P  [SD_TAIT_11_SMD_ST_285_2]  18.87 14.21 270 top
CN1300  LOTES_APCI0062-P001A_NGFF_E_KEY_75P  [MPCI_LOTES_75_050_RV_198]  42.08 128.7 180 bottom
